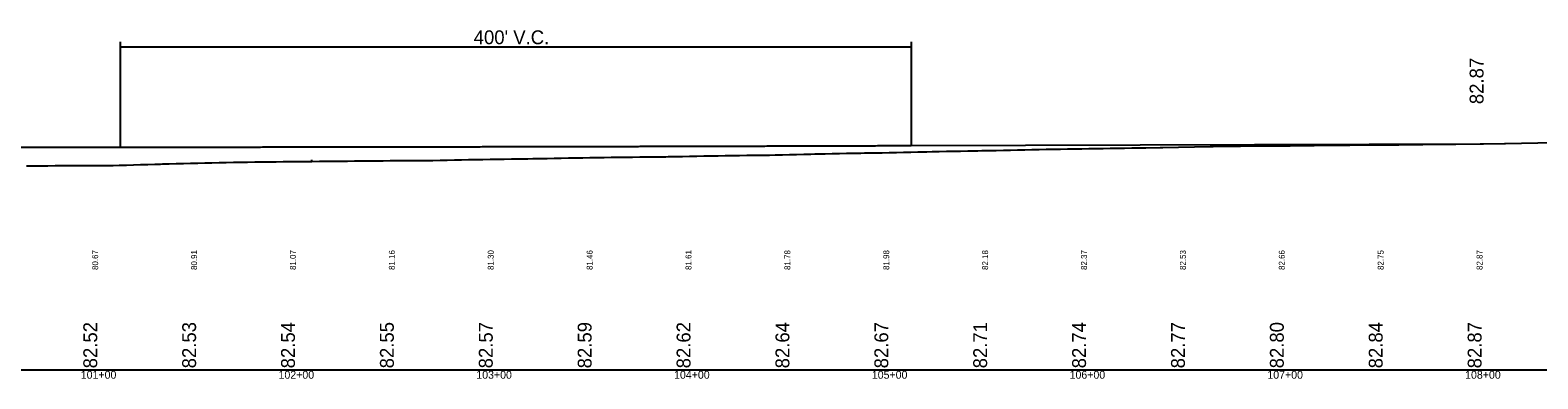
# Model space of a CAD drawing. Extents: x 1592 to 6065, y -1942 to -1437.
# Drawn here: x 4185 to 4947, y -1942 to -1766 of the extents above; entities that cross this region are included whole.
import ezdxf

# ---------------------------------------------------------------- set-up
doc = ezdxf.new("R2010")
doc.units = 0
for name, color, linetype in [('Default', 7, 'Continuous'), ('RD_DDB_Profile_EX', 7, 'Continuous'), ('RD_DDB_Profile_Lbl', 7, 'Continuous'), ('RD_DDB_Profile_PR', 7, 'Continuous'), ('RD_DDB_StaTX', 7, 'Continuous'), ('RD_DDB_StripGrade', 7, 'Continuous'), ('RD_DDB_VCLbl', 7, 'Continuous'), ('RD_GPK_Profile_Cell', 7, 'Continuous')]:
    doc.layers.add(name, color=color, linetype=linetype)

msp = doc.modelspace()

# ---------------------------------------------------------------- linework, layer by layer
at = {"layer": 'Default'}
msp.add_line((4327.26, -1831.92), (4327.26, -1831.09), dxfattribs=at)
at = {"layer": 'RD_DDB_Profile_EX'}
for points in [[(4323.65, -1831.95), (4327.26, -1831.92), (4331.17, -1831.89), (4333.24, -1831.88), (4334.47, -1831.86), (4338.07, -1831.82), (4341.68, -1831.78), (4345.28, -1831.75), (4348.89, -1831.71), (4352.5, -1831.68), (4356.1, -1831.65), (4358.15, -1831.63), (4358.63, -1831.63), (4359.71, -1831.62), (4363.31, -1831.6), (4366.92, -1831.57), (4370.52, -1831.55), (4374.13, -1831.54), (4377.73, -1831.52), (4381.34, -1831.51), (4383.18, -1831.5), (4384.94, -1831.5), (4385.86, -1831.5), (4386.4, -1831.5), (4386.9, -1831.49), (4388.55, -1831.45), (4392.15, -1831.37), (4395.76, -1831.29), (4399.36, -1831.21), (4402.97, -1831.14), (4406.57, -1831.06), (4410.18, -1830.99), (4411.39, -1830.97), (4411.97, -1830.96), (4413.79, -1830.93), (4417.39, -1830.87), (4421, -1830.8), (4424.6, -1830.74), (4428.21, -1830.69), (4431.81, -1830.63), (4435.42, -1830.58), (4436.51, -1830.56), (4439.02, -1830.53), (4442.63, -1830.48), (4443.73, -1830.46), (4446.23, -1830.42), (4449.84, -1830.35), (4453.44, -1830.28), (4457.05, -1830.22), (4460.65, -1830.16), (4464.26, -1830.1), (4467.86, -1830.04), (4468.56, -1830.03), (4469.79, -1830.01), (4471.47, -1829.98), (4475.08, -1829.93), (4478.68, -1829.88), (4482.29, -1829.83), (4485.89, -1829.79), (4489.5, -1829.75), (4493.1, -1829.71), (4493.56, -1829.7), (4494.17, -1829.69), (4496.71, -1829.67), (4500.31, -1829.63), (4503.92, -1829.6), (4504.89, -1829.59), (4506.25, -1829.55), (4507.52, -1829.52), (4511.13, -1829.45), (4514.73, -1829.38), (4518.34, -1829.32), (4521.94, -1829.25), (4525.55, -1829.19), (4529.15, -1829.14), (4529.87, -1829.12), (4531.64, -1829.08), (4532.76, -1829.06), (4536.37, -1829.01), (4539.97, -1828.96), (4543.58, -1828.91), (4547.18, -1828.87), (4550.79, -1828.82), (4554.39, -1828.79), (4554.89, -1828.78), (4555.2, -1828.77), (4558, -1828.75), (4558.67, -1828.74), (4561.6, -1828.66), (4565.21, -1828.56), (4568.81, -1828.47), (4572.42, -1828.38), (4576.02, -1828.3), (4579.63, -1828.21), (4581.66, -1828.17), (4583.23, -1828.14), (4583.68, -1828.14), (4586.84, -1828.07), (4590.44, -1827.99), (4594.05, -1827.92), (4597.66, -1827.85)], [(4597.66, -1827.85), (4601.26, -1827.78), (4604.87, -1827.72), (4606.67, -1827.69), (4608.93, -1827.66), (4612.08, -1827.61), (4612.59, -1827.6), (4614.51, -1827.58), (4615.68, -1827.55), (4619.29, -1827.46), (4622.89, -1827.37), (4626.5, -1827.29), (4630.1, -1827.21), (4633.71, -1827.13), (4637.57, -1827.05), (4638.33, -1827.04), (4640.92, -1826.99), (4644.52, -1826.92), (4648.13, -1826.85), (4651.73, -1826.78), (4655.34, -1826.71), (4658.95, -1826.65), (4661, -1826.62), (4662.61, -1826.57), (4664.06, -1826.53), (4666.16, -1826.5), (4669.76, -1826.44), (4673.37, -1826.39), (4676.97, -1826.34), (4677.5, -1826.33), (4680.58, -1826.26), (4684.18, -1826.17), (4687.79, -1826.08), (4691.39, -1826), (4695, -1825.91), (4698.6, -1825.84), (4700.37, -1825.8), (4702.5, -1825.8), (4705.81, -1825.73), (4709.42, -1825.66), (4713.02, -1825.59), (4716.63, -1825.52), (4720.24, -1825.45), (4723.84, -1825.39), (4725.83, -1825.36), (4727.51, -1825.36), (4731.05, -1825.3), (4732.24, -1825.28), (4732.55, -1825.28), (4734.66, -1825.25), (4738.26, -1825.18), (4741.87, -1825.12), (4745.47, -1825.06), (4749.08, -1825), (4756.28, -1824.88), (4757.55, -1824.88), (4781.6, -1824.49), (4782.55, -1824.48), (4783.06, -1824.48), (4796.19, -1824.26), (4796.95, -1824.27), (4821.19, -1824.03), (4821.93, -1824.04), (4846.33, -1823.8), (4851.35, -1823.75), (4852.08, -1823.75), (4876.36, -1823.5), (4876.86, -1823.5), (4901.36, -1823.25), (4905.81, -1823.21), (4930.44, -1822.82), (4930.82, -1822.82), (4955.3, -1822.44)], [(4183.05, -1834.19), (4186.65, -1834.16), (4190.26, -1834.13), (4193.86, -1834.11), (4197.47, -1834.09), (4198.05, -1834.09), (4198.92, -1834.07), (4201.07, -1834.06), (4204.68, -1834.04), (4208.28, -1834.03), (4211.89, -1834.02), (4215.49, -1834.01), (4219.1, -1834), (4222.7, -1834), (4223.2, -1834), (4226.31, -1834), (4226.76, -1834), (4229.92, -1833.9), (4233.52, -1833.78), (4237.13, -1833.67), (4240.73, -1833.56), (4244.34, -1833.45), (4247.94, -1833.34), (4250.84, -1833.26), (4251.77, -1833.24), (4255.15, -1833.14), (4258.76, -1833.05), (4262.36, -1832.95), (4265.97, -1832.86), (4269.57, -1832.77), (4273.18, -1832.68), (4276.2, -1832.61), (4276.78, -1832.6), (4280.39, -1832.51), (4281.16, -1832.5), (4281.57, -1832.49), (4283.99, -1832.45), (4287.6, -1832.39), (4291.21, -1832.34), (4294.81, -1832.29), (4298.42, -1832.24), (4302.02, -1832.19), (4305.63, -1832.14), (4306.16, -1832.14), (4306.83, -1832.13), (4309.23, -1832.1), (4312.84, -1832.06), (4316.44, -1832.02), (4320.05, -1831.99), (4323.65, -1831.95)]]:
    msp.add_lwpolyline(points, dxfattribs=at)
at = {"layer": 'RD_DDB_Profile_PR'}
for p, q in [((4071.68, -1824.84), (4230.39, -1824.72)), ((4630.39, -1823.93), (4919.75, -1822.99))]:
    msp.add_line(p, q, dxfattribs=at)
msp.add_spline([(4230.39, -1824.72), (4238.39, -1824.72), (4246.39, -1824.71), (4254.39, -1824.71), (4262.39, -1824.7), (4270.39, -1824.69), (4278.39, -1824.68), (4286.39, -1824.68), (4294.39, -1824.67), (4302.39, -1824.66), (4310.39, -1824.65), (4318.39, -1824.64), (4326.39, -1824.63), (4334.39, -1824.62), (4342.39, -1824.61), (4350.39, -1824.59), (4358.39, -1824.58), (4366.39, -1824.57), (4374.39, -1824.56), (4382.39, -1824.54), (4390.39, -1824.53), (4398.39, -1824.52), (4406.39, -1824.5), (4414.39, -1824.49), (4422.39, -1824.47), (4430.39, -1824.46), (4438.39, -1824.44), (4446.39, -1824.42), (4454.39, -1824.41), (4462.39, -1824.39), (4470.39, -1824.37), (4478.39, -1824.35), (4486.39, -1824.34), (4494.39, -1824.32), (4502.39, -1824.3), (4510.39, -1824.28), (4518.39, -1824.26), (4526.39, -1824.24), (4534.39, -1824.22), (4542.39, -1824.19), (4550.39, -1824.17), (4558.39, -1824.15), (4566.39, -1824.13), (4574.39, -1824.11), (4582.39, -1824.08), (4590.39, -1824.06), (4598.39, -1824.03), (4606.39, -1824.01), (4614.39, -1823.98), (4622.39, -1823.96), (4630.39, -1823.93)], degree=3, dxfattribs=at)
at = {"layer": 'RD_DDB_VCLbl'}
for p, q in [((4230.39, -1771.43), (4230.39, -1824.72)), ((4230.39, -1773.93), (4630.39, -1773.93)), ((4630.39, -1771.43), (4630.39, -1823.93))]:
    msp.add_line(p, q, dxfattribs=at)
at = {"layer": 'RD_GPK_Profile_Cell'}
msp.add_line((1619.75, -1937.33), (6065.43, -1937.33), dxfattribs=at)

# ---------------------------------------------------------------- texts
at = {"layer": 'RD_DDB_Profile_Lbl'}
msp.add_text('82.87', height=7, rotation=90, dxfattribs=at).set_placement((4919.75, -1802.99))
at = {"layer": 'RD_DDB_StaTX'}
for s, p in [('101+00', (4210.46, -1941.83)), ('102+00', (4310.46, -1941.83)), ('103+00', (4410.46, -1941.83)), ('104+00', (4510.46, -1941.83)), ('105+00', (4610.46, -1941.83)), ('106+00', (4710.46, -1941.83)), ('107+00', (4810.46, -1941.83)), ('108+00', (4910.46, -1941.83))]:
    msp.add_text(s, height=4, dxfattribs=at).set_placement(p)
at = {"layer": 'RD_DDB_StripGrade'}
for s, height, p in [('80.67', 3, (4219.25, -1886.83)), ('80.91', 3, (4269.25, -1886.83)), ('81.07', 3, (4319.25, -1886.83)), ('81.16', 3, (4369.25, -1886.83)), ('81.30', 3, (4419.25, -1886.83)), ('81.46', 3, (4469.25, -1886.83)), ('81.61', 3, (4519.25, -1886.83)), ('81.78', 3, (4569.25, -1886.83)), ('81.98', 3, (4619.25, -1886.83)), ('82.18', 3, (4669.25, -1886.83)), ('82.37', 3, (4719.25, -1886.83)), ('82.53', 3, (4769.25, -1886.83)), ('82.66', 3, (4819.25, -1886.83)), ('82.75', 3, (4869.25, -1886.83)), ('82.87', 3, (4919.25, -1886.83)), ('82.54', 7, (4318.75, -1936.58)), ('82.64', 7, (4568.75, -1936.58)), ('82.74', 7, (4718.75, -1936.58)), ('82.80', 7, (4818.75, -1936.58)), ('82.84', 7, (4868.75, -1936.58)), ('82.52', 7, (4218.75, -1936.58)), ('82.53', 7, (4268.75, -1936.58)), ('82.55', 7, (4368.75, -1936.58)), ('82.57', 7, (4418.75, -1936.58)), ('82.59', 7, (4468.75, -1936.58)), ('82.62', 7, (4518.75, -1936.58)), ('82.67', 7, (4618.75, -1936.58)), ('82.71', 7, (4668.75, -1936.58)), ('82.77', 7, (4768.75, -1936.58)), ('82.87', 7, (4918.75, -1936.58))]:
    msp.add_text(s, height=height, rotation=90, dxfattribs=at).set_placement(p)
at = {"layer": 'RD_DDB_VCLbl'}
msp.add_text("400' V.C.", height=7, dxfattribs=at).set_placement((4409.14, -1772.68))

doc.saveas('drawing.dxf')
